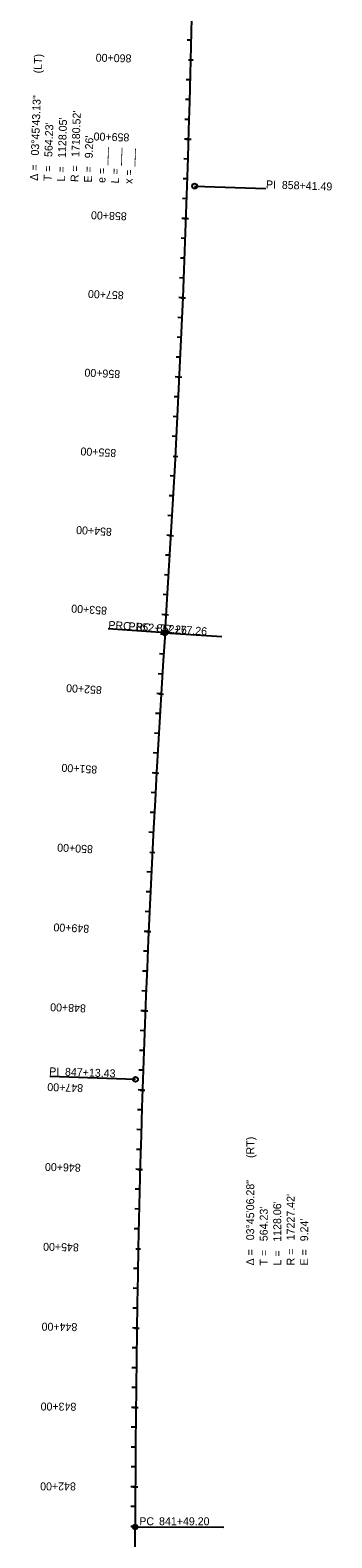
# Model space of a CAD drawing. Extents: x 18543252 to 18543633, y 7433057 to 7440612.
# Drawn here: x 18543252 to 18543633, y 7434928 to 7436828 of the extents above; entities that cross this region are included whole.
import ezdxf

# ---------------------------------------------------------------- set-up
doc = ezdxf.new("R2010")
doc.units = 0
for name, color, linetype in [('PS_BOLT', 7, 'Continuous'), ('PS_DIM', 7, 'Continuous'), ('PS_MID', 7, 'Continuous'), ('PS_SHAPE', 7, 'Continuous')]:
    doc.layers.add(name, color=color, linetype=linetype)

msp = doc.modelspace()

# ---------------------------------------------------------------- linework, layer by layer
at = {"layer": 'PS_BOLT'}
for p, q in [((18543452, 7436790.8), (18543458.1, 7436790.7)), ((18543452.4, 7436690.8), (18543446.9, 7436691)), ((18543449.1, 7436590.9), (18543443.6, 7436591)), ((18543445.2, 7436490.9), (18543439.8, 7436491.2)), ((18543440.8, 7436391), (18543435.3, 7436391.3)), ((18543432.7, 7436291.3), (18543438.8, 7436291)), ((18543430.2, 7436191.3), (18543424.7, 7436191.6)), ((18543424, 7436091.5), (18543418.5, 7436091.9)), ((18543417.6, 7435991.7), (18543412.1, 7435992)), ((18543411.7, 7435891.9), (18543406.2, 7435892.2)), ((18543403.3, 7435792.2), (18543409.4, 7435791.9)), ((18543401.7, 7435692.1), (18543396.2, 7435692.4)), ((18543397.5, 7435592.2), (18543392.1, 7435592.4)), ((18543394, 7435492.3), (18543388.5, 7435492.5)), ((18543391, 7435392.3), (18543385.6, 7435392.5)), ((18543385.6, 7435292.4), (18543391.7, 7435292.3)), ((18543386.8, 7435192.4), (18543381.4, 7435192.5)), ((18543385.6, 7435092.4), (18543380.1, 7435092.4)), ((18543384.9, 7434992.4), (18543379.5, 7434992.4))]:
    msp.add_line(p, q, dxfattribs=at)
at = {"layer": 'PS_DIM'}
for p, q in [((18543459.8, 7436631.8), (18543549.7, 7436628.8)), ((18543422.5, 7436068.8), (18543350.6, 7436073.6)), ((18543422.5, 7436068.8), (18543494.3, 7436064)), ((18543385.2, 7435505.8), (18543277.1, 7435509.4)), ((18543384.8, 7434941.6), (18543496.8, 7434941.5))]:
    msp.add_line(p, q, dxfattribs=at)
for centre in [(18543459.8, 7436631.8), (18543422.5, 7436068.8), (18543422.5, 7436068.8), (18543385.2, 7435505.8), (18543384.8, 7434941.6)]:
    msp.add_circle(centre, 3.12, dxfattribs=at)
at = {"layer": 'PS_MID'}
for p, q in [((18543455.7, 7436815.8), (18543450.2, 7436815.9)), ((18543452, 7436790.8), (18543458.1, 7436790.7)), ((18543454.4, 7436765.8), (18543449, 7436765.9)), ((18543453.8, 7436740.8), (18543448.3, 7436740.9)), ((18543453.1, 7436715.8), (18543447.6, 7436715.9)), ((18543449.3, 7436690.9), (18543455.4, 7436690.7)), ((18543451.6, 7436665.8), (18543446.1, 7436666)), ((18543450.8, 7436640.8), (18543445.3, 7436641)), ((18543450, 7436615.8), (18543444.5, 7436616)), ((18543446, 7436591), (18543452.1, 7436590.7)), ((18543448.2, 7436565.9), (18543442.7, 7436566.1)), ((18543447.2, 7436540.9), (18543441.8, 7436541.1)), ((18543446.3, 7436515.9), (18543440.8, 7436516.1)), ((18543442.2, 7436491.1), (18543448.3, 7436490.8)), ((18543444.2, 7436465.9), (18543438.7, 7436466.2)), ((18543443.1, 7436441), (18543437.6, 7436441.2)), ((18543442, 7436416), (18543436.5, 7436416.2)), ((18543437.7, 7436391.2), (18543443.8, 7436390.9)), ((18543439.6, 7436366.1), (18543434.1, 7436366.3)), ((18543438.4, 7436341.1), (18543432.9, 7436341.4)), ((18543437.1, 7436316.1), (18543431.6, 7436316.4)), ((18543432.7, 7436291.3), (18543438.8, 7436291)), ((18543434.4, 7436266.2), (18543429, 7436266.5)), ((18543433, 7436241.2), (18543427.6, 7436241.5)), ((18543431.6, 7436216.3), (18543426.2, 7436216.6)), ((18543427.1, 7436191.5), (18543433.2, 7436191.1)), ((18543428.7, 7436166.4), (18543423.2, 7436166.7)), ((18543427.1, 7436141.4), (18543421.7, 7436141.7)), ((18543425.6, 7436116.4), (18543420.1, 7436116.8)), ((18543420.9, 7436091.7), (18543427, 7436091.3)), ((18543422.3, 7436066.6), (18543416.9, 7436066.9)), ((18543420.7, 7436041.6), (18543415.3, 7436042)), ((18543419.1, 7436016.7), (18543413.7, 7436017)), ((18543414.5, 7435991.9), (18543420.6, 7435991.5)), ((18543416, 7435966.8), (18543410.6, 7435967.1)), ((18543414.5, 7435941.8), (18543409.1, 7435942.1)), ((18543413.1, 7435916.8), (18543407.6, 7435917.2)), ((18543408.6, 7435892.1), (18543414.7, 7435891.7)), ((18543410.3, 7435866.9), (18543404.9, 7435867.2)), ((18543409, 7435842), (18543403.5, 7435842.2)), ((18543407.7, 7435817), (18543402.2, 7435817.3)), ((18543403.3, 7435792.2), (18543409.4, 7435791.9)), ((18543405.2, 7435767.1), (18543399.7, 7435767.3)), ((18543404, 7435742.1), (18543398.5, 7435742.3)), ((18543402.8, 7435717.1), (18543397.4, 7435717.4)), ((18543398.6, 7435692.3), (18543404.7, 7435692)), ((18543400.6, 7435667.2), (18543395.1, 7435667.4)), ((18543399.5, 7435642.2), (18543394.1, 7435642.4)), ((18543398.5, 7435617.2), (18543393.1, 7435617.4)), ((18543394.5, 7435592.3), (18543400.6, 7435592.1)), ((18543396.6, 7435567.2), (18543391.2, 7435567.4)), ((18543395.7, 7435542.3), (18543390.2, 7435542.4)), ((18543394.8, 7435517.3), (18543389.4, 7435517.5)), ((18543390.9, 7435492.4), (18543397.1, 7435492.2)), ((18543393.2, 7435467.3), (18543387.7, 7435467.5)), ((18543392.4, 7435442.3), (18543387, 7435442.5)), ((18543391.7, 7435417.3), (18543386.3, 7435417.5)), ((18543388, 7435392.4), (18543394.1, 7435392.2)), ((18543390.4, 7435367.3), (18543384.9, 7435367.5)), ((18543389.8, 7435342.3), (18543384.3, 7435342.5)), ((18543389.2, 7435317.3), (18543383.7, 7435317.5)), ((18543385.6, 7435292.4), (18543391.7, 7435292.3)), ((18543388.1, 7435267.4), (18543382.7, 7435267.5)), ((18543387.7, 7435242.4), (18543382.2, 7435242.5)), ((18543387.2, 7435217.4), (18543381.8, 7435217.5)), ((18543383.8, 7435192.4), (18543389.9, 7435192.3)), ((18543386.5, 7435167.4), (18543381, 7435167.4)), ((18543386.1, 7435142.4), (18543380.7, 7435142.4)), ((18543385.8, 7435117.4), (18543380.4, 7435117.4)), ((18543382.5, 7435092.4), (18543388.7, 7435092.3)), ((18543385.4, 7435067.4), (18543379.9, 7435067.4)), ((18543385.2, 7435042.4), (18543379.7, 7435042.4)), ((18543385.1, 7435017.4), (18543379.6, 7435017.4)), ((18543381.9, 7434992.4), (18543388, 7434992.4)), ((18543384.9, 7434967.4), (18543379.4, 7434967.4)), ((18543384.8, 7434942.4), (18543379.4, 7434942.4))]:
    msp.add_line(p, q, dxfattribs=at)
at = {"layer": 'PS_SHAPE'}
msp.add_line((18543383.6, 7433059.8), (18543384.8, 7434941.6), dxfattribs=at)
for centre, radius, start, end in [((18526279.5, 7437204.1), 17180.5, 356.21104, 359.97302), ((18560612.3, 7434930.4), 17227.4, 176.21104, 179.96279)]:
    msp.add_arc(centre, radius, start, end, dxfattribs=at)

# ---------------------------------------------------------------- texts
at = {"layer": 'PS_BOLT'}
for s, rotation, p in [('860+00', 178.6213, (18543380.2, 7436797.6)), ('855+00', 176.9539, (18543361.1, 7436300.1)), ('850+00', 177.1332, (18543331.7, 7435800.8)), ('845+00', 178.7961, (18543313.8, 7435298.9))]:
    msp.add_text(s, height=10.02, rotation=rotation, dxfattribs=at).set_placement(p)
at = {"layer": 'PS_DIM'}
for s, rotation, p in [(' (LT)', 88.092, (18543266.5, 7436770)), ('03°45\'43.13"', 88.092, (18543263.2, 7436670.1)), ("564.23'", 88.092, (18543280.2, 7436668.3)), ("1128.05'", 88.092, (18543297.2, 7436667.1)), ("17180.52'", 88.092, (18543314.3, 7436668.3)), ("9.26'", 88.092, (18543331.2, 7436666.6)), ('e = ___ ', 88.092, (18543347.2, 7436635.6)), ('L = ___', 88.092, (18543364.3, 7436635)), ('x = ___', 88.092, (18543381.3, 7436634.4)), ('Δ = ', 88.092, (18543262.1, 7436638.4)), ('T = ', 88.092, (18543279.1, 7436637.8)), ('L = ', 88.092, (18543296.2, 7436637.3)), ('R = ', 88.092, (18543313.2, 7436636.7)), ('E = ', 88.092, (18543330.2, 7436636.1)), ('PI ', 358.092, (18543549.7, 7436629)), ('858+41.49', 358.092, (18543569.7, 7436628.3)), ('PRC', 356.211, (18543350.7, 7436073.8)), ('PRC', 356.211, (18543376.1, 7436072.1)), ('852+77.26', 356.211, (18543386.1, 7436071.4)), ('852+77.26', 356.211, (18543411.6, 7436069.7)), ('PI ', 358.0869, (18543276.2, 7435511)), ('847+13.43', 358.0869, (18543296.1, 7435510.4)), (' (RT)', 89.9628, (18543535, 7435403)), ('03°45\'06.28"', 89.9628, (18543534.9, 7435303)), ("17227.42'", 89.9628, (18543586, 7435302.9)), ("564.23'", 89.9628, (18543552, 7435301.8)), ("1128.06'", 89.9628, (18543569, 7435301.1)), ("9.24'", 89.9628, (18543603.1, 7435301.7)), ('Δ = ', 89.9628, (18543534.9, 7435271.3)), ('T = ', 89.9628, (18543551.9, 7435271.3)), ('L = ', 89.9628, (18543569, 7435271.3)), ('R = ', 89.9628, (18543586, 7435271.3)), ('E = ', 89.9628, (18543603, 7435271.3)), ('PC', 359.9628, (18543390, 7434943.8)), ('841+49.20', 359.9628, (18543414.9, 7434943.8))]:
    msp.add_text(s, height=10.02, rotation=rotation, dxfattribs=at).set_placement(p)
at = {"layer": 'PS_MID'}
for s, rotation, p in [('860+00', 178.6213, (18543380.2, 7436797.6)), ('859+00', 178.2878, (18543377.6, 7436698)), ('858+00', 177.9544, (18543374.3, 7436598.5)), ('857+00', 177.6209, (18543370.5, 7436499)), ('856+00', 177.2874, (18543366.1, 7436399.6)), ('855+00', 176.9539, (18543361.1, 7436300.1)), ('854+00', 176.6204, (18543355.6, 7436200.7)), ('853+00', 176.2869, (18543349.5, 7436101.4)), ('852+00', 176.468, (18543343, 7436001.3)), ('851+00', 176.8006, (18543337.1, 7435901.1)), ('850+00', 177.1332, (18543331.7, 7435800.8)), ('849+00', 177.4657, (18543327, 7435700.5)), ('848+00', 177.7983, (18543322.8, 7435600.1)), ('847+00', 178.1309, (18543319.2, 7435499.7)), ('846+00', 178.4635, (18543316.2, 7435399.3)), ('845+00', 178.7961, (18543313.8, 7435298.9)), ('844+00', 179.1287, (18543311.9, 7435198.5)), ('843+00', 179.4613, (18543310.6, 7435098.1)), ('842+00', 179.7938, (18543310, 7434997.7))]:
    msp.add_text(s, height=10.02, rotation=rotation, dxfattribs=at).set_placement(p)

doc.saveas('drawing.dxf')
